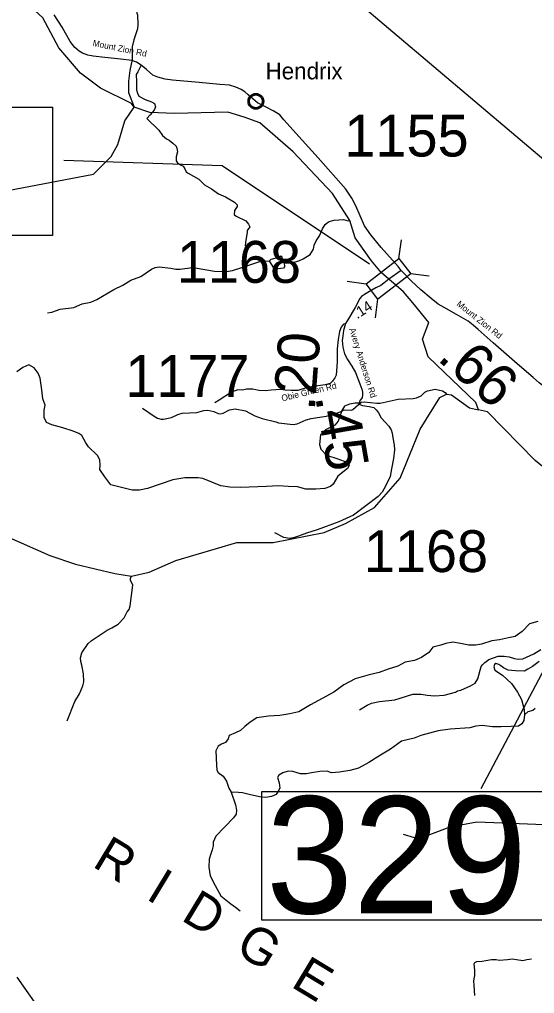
# Model space of a CAD drawing. Extents: x 1248224 to 1454986, y 825081 to 985870.
# Drawn here: x 1284414 to 1290579, y 869090 to 880743 of the extents above; entities that cross this region are included whole.
import ezdxf

# ---------------------------------------------------------------- set-up
doc = ezdxf.new("R2010")
doc.units = 0
for name, color, linetype in [('Exist Civil Demographics Community CELL', 7, 'Continuous'), ('Exist Civil Demographics Community Label', 7, 'Continuous'), ('Exist Geographical Mountain Summit Label', 7, 'Continuous'), ('Exist Hydrographic Creek Single Shore', 7, 'Continuous'), ('Exist Hydrographic Misc Water Feature', 7, 'Continuous'), ('Exist Road Non-System Type 51', 7, 'Continuous'), ('Exist Road Secondary Mileage Hundredths English Label', 7, 'Continuous'), ('Exist Road Secondary Structure Standard Bridge CELL', 7, 'Continuous'), ('Exist Road Secondary Structure Standard Bridge Number Label', 7, 'Continuous'), ('Exist Road Secondary Type 41 Attributed', 7, 'Continuous'), ('Exist Road Secondary Type 51 Attributed', 7, 'Continuous'), ('Exist Road Secondary Type 51 Label', 7, 'Continuous'), ('Exist Road Secondary Type 51 Number Label', 7, 'Continuous')]:
    doc.layers.add(name, color=color, linetype=linetype)

msp = doc.modelspace()

# ---------------------------------------------------------------- linework, layer by layer
at = {"layer": 'Exist Civil Demographics Community CELL'}
msp.add_lwpolyline([(1287166, 879777), (1287167, 879782), (1287169, 879789), (1287172, 879796), (1287175, 879802), (1287178, 879808), (1287182, 879813), (1287186, 879817), (1287190, 879822), (1287196, 879826), (1287201, 879830), (1287206, 879833), (1287211, 879835), (1287217, 879838), (1287222, 879840), (1287227, 879841), (1287231, 879841), (1287236, 879842), (1287242, 879842), (1287246, 879842), (1287252, 879842), (1287257, 879841), (1287262, 879840), (1287267, 879839), (1287272, 879837), (1287279, 879834), (1287285, 879831), (1287290, 879827), (1287295, 879823), (1287299, 879820), (1287303, 879815), (1287307, 879811), (1287310, 879806), (1287313, 879801), (1287315, 879796), (1287317, 879791), (1287319, 879786), (1287320, 879781), (1287321, 879775), (1287322, 879771), (1287322, 879765), (1287322, 879759), (1287321, 879753), (1287320, 879748), (1287319, 879742), (1287317, 879736), (1287315, 879731), (1287311, 879725), (1287308, 879719), (1287305, 879715), (1287300, 879710), (1287295, 879705), (1287290, 879701), (1287285, 879697), (1287281, 879695), (1287274, 879692), (1287267, 879689), (1287261, 879687), (1287254, 879686), (1287250, 879686), (1287245, 879685), (1287240, 879685), (1287235, 879686), (1287230, 879687), (1287224, 879688), (1287219, 879689), (1287214, 879691), (1287210, 879693), (1287206, 879695), (1287199, 879699), (1287193, 879704), (1287188, 879708), (1287184, 879713), (1287181, 879717), (1287178, 879721), (1287174, 879728), (1287172, 879732), (1287170, 879736), (1287168, 879744), (1287166, 879751), (1287165, 879756), (1287165, 879762), (1287165, 879767), (1287166, 879774)], close=True, dxfattribs=at)
for centre, radius in [((1287244, 879764), 94.3), ((1287243, 879765), 76.7)]:
    msp.add_circle(centre, radius, dxfattribs=at)
at = {"layer": 'Exist Hydrographic Creek Single Shore'}
for points in [[(1285786, 879695), (1285754, 879739), (1285383, 879923), (1285146, 880102), (1284886, 880403), (1284695, 880764), (1284597, 880852), (1284299, 880923), (1283948, 880907), (1283420, 881148)], [(1288835, 877637), (1288749, 877713), (1288629, 877856), (1288433, 878129), (1288367, 878339), (1288162, 878663), (1287691, 879158), (1287291, 879508), (1287103, 879576), (1286907, 879635), (1286268, 879617), (1285976, 879632), (1285786, 879695)], [(1289908, 876074), (1289877, 876160), (1289307, 876706), (1289237, 876918), (1289312, 877116), (1289122, 877354), (1289009, 877484), (1288835, 877637)], [(1292628, 873989), (1292480, 873916), (1292339, 873798), (1292149, 873939), (1291946, 874109), (1291864, 874236), (1291719, 874279), (1291609, 874359), (1291494, 874427), (1291324, 874630), (1291193, 874741), (1291112, 874855), (1291068, 875072), (1290585, 875466), (1290016, 876049), (1289908, 876074)], [(1284678, 868871), (1284388, 869284)]]:
    msp.add_lwpolyline(points, dxfattribs=at)
at = {"layer": 'Exist Hydrographic Misc Water Feature'}
for points in [[(1285848, 881734), (1285875, 881701), (1285910, 881636), (1285916, 881557), (1285882, 881393), (1285876, 881313), (1285822, 881184), (1285813, 881141), (1285813, 880884), (1285820, 880820), (1285827, 880800), (1285830, 880683), (1285825, 880632), (1285782, 880499), (1285762, 880416), (1285762, 880263), (1285733, 880134), (1285718, 880006), (1285720, 879870), (1285786, 879695)], [(1280564, 876573), (1281221, 877164), (1281561, 877423), (1281746, 877495), (1282014, 877535), (1282115, 877586), (1282277, 877730), (1282735, 878020), (1282961, 878088), (1283182, 878251), (1283385, 878361), (1283657, 878563), (1283766, 878603), (1285299, 878891), (1285513, 879103), (1285592, 879249), (1285674, 879530), (1285786, 879695)], [(1287582, 877831), (1287670, 877831), (1287758, 877857), (1287809, 877880), (1287894, 877931), (1287932, 877994), (1287941, 878042), (1287966, 878097), (1288004, 878156), (1288040, 878238), (1288073, 878289), (1288098, 878312), (1288122, 878328), (1288179, 878342), (1288291, 878350), (1288350, 878336), (1288367, 878339)], [(1287582, 877831), (1287570, 877847), (1287559, 877899), (1287543, 877912), (1287515, 877896), (1287422, 877871), (1287406, 877855)], [(1284749, 877232), (1284801, 877241), (1284902, 877278), (1285063, 877296), (1285164, 877342), (1285268, 877361), (1285341, 877392), (1285542, 877512), (1285652, 877566), (1285745, 877625), (1285866, 877667), (1285995, 877758), (1286039, 877776), (1286087, 877784), (1286227, 877770), (1286287, 877757), (1286339, 877756), (1286479, 877774), (1286515, 877773), (1286747, 877733), (1286891, 877730), (1286963, 877742), (1287076, 877775), (1287290, 877848), (1287406, 877855)], [(1287582, 877831), (1287588, 877785), (1287574, 877767), (1287484, 877757), (1287464, 877766), (1287406, 877855)], [(1284227, 874575), (1284779, 874332), (1285085, 874227), (1285557, 874113), (1285756, 874081), (1285966, 874131), (1286287, 874272), (1287017, 874487), (1287451, 874485), (1288063, 874604), (1288315, 874714), (1288662, 874904), (1288971, 875255), (1289210, 875842), (1289445, 876221), (1289526, 876262), (1289587, 876251), (1289800, 876096), (1289908, 876074)], [(1285888, 876093), (1286026, 875997), (1286065, 875974), (1286109, 875961), (1286137, 875961), (1286233, 875982), (1286310, 876019), (1286363, 876033), (1286535, 876043), (1286619, 876065), (1286668, 876068), (1286739, 876054), (1286791, 876029), (1286815, 876027), (1286851, 876033), (1286926, 876075), (1286994, 876086), (1287118, 876061), (1287230, 876002), (1287318, 875968), (1287481, 875930), (1287513, 875917), (1287688, 875898), (1287736, 875906), (1287846, 875953), (1287906, 875971), (1288083, 875997), (1288165, 876019), (1288266, 876053), (1288299, 876072), (1288387, 876071), (1288403, 876079), (1288505, 876165), (1288541, 876170), (1288693, 876151), (1288733, 876153), (1288947, 876202), (1289127, 876208), (1289167, 876215), (1289224, 876241), (1289267, 876286), (1289299, 876302), (1289388, 876319), (1289479, 876301), (1289511, 876282), (1289526, 876262)], [(1285159, 873165), (1285234, 873277), (1285271, 873310), (1285464, 873437), (1285521, 873463), (1285594, 873509), (1285668, 873585), (1285702, 873656), (1285725, 873683), (1285738, 873727), (1285770, 873975), (1285743, 874035), (1285744, 874057), (1285756, 874081)], [(1284985, 872354), (1285077, 872583), (1285131, 872676), (1285174, 872771), (1285185, 872819), (1285179, 872915), (1285162, 873020), (1285147, 873060), (1285146, 873104), (1285159, 873165)], [(1289986, 873049), (1290033, 873086), (1290142, 873127), (1290214, 873127), (1290274, 873118), (1290341, 873096), (1290385, 873091), (1290441, 873095), (1290571, 873152), (1290654, 873204)], [(1288483, 872484), (1288576, 872541), (1288629, 872564), (1288725, 872584), (1288906, 872603), (1289124, 872672), (1289224, 872673), (1289296, 872658), (1289383, 872652), (1289496, 872661), (1289633, 872696), (1289657, 872712), (1289697, 872718), (1289811, 872772), (1289869, 872804), (1289899, 872855), (1289939, 873004), (1289955, 873023), (1289986, 873049)], [(1289008, 870997), (1289140, 870955), (1289324, 870991), (1289569, 871084), (1289887, 871143), (1291103, 871096)]]:
    msp.add_lwpolyline(points, dxfattribs=at)
at = {"layer": 'Exist Road Non-System Type 51'}
for points in [[(1285869, 880195), (1285831, 880116), (1285812, 880086), (1285814, 879997), (1285814, 879902), (1285825, 879861), (1285844, 879826), (1285917, 879788), (1285996, 879758), (1286031, 879739), (1286042, 879698), (1286028, 879658), (1285977, 879604), (1285939, 879558), (1286080, 879421), (1286126, 879355), (1286175, 879315), (1286207, 879299), (1286248, 879263), (1286288, 879228), (1286299, 879204), (1286307, 879158), (1286288, 879101), (1286288, 879052), (1286305, 879027), (1286343, 879003), (1286372, 878989), (1286394, 878957), (1286410, 878922), (1286435, 878905), (1286559, 878832), (1286627, 878767), (1286714, 878716), (1286798, 878656), (1286879, 878621), (1286987, 878556), (1287019, 878524), (1287019, 878505), (1286989, 878457), (1286984, 878410), (1287008, 878389), (1287122, 878335), (1287157, 878294), (1287171, 878264), (1287141, 878218), (1287138, 878199), (1287119, 878077), (1287117, 878031)], [(1288481, 876154), (1288434, 876153), (1288365, 876142), (1288304, 876117), (1288271, 876066), (1288227, 875939), (1288187, 875888), (1288078, 875833), (1288017, 875775), (1288006, 875659), (1288020, 875601), (1288089, 875532), (1288213, 875492), (1288300, 875459), (1288351, 875441), (1288362, 875408), (1288340, 875372), (1288224, 875281), (1288169, 875183), (1288137, 875157), (1288071, 875132), (1287962, 875125), (1287842, 875125), (1287741, 875150), (1287632, 875157), (1287515, 875165), (1287370, 875154), (1287061, 875143), (1286931, 875146), (1286825, 875165), (1286607, 875252), (1286553, 875259), (1286393, 875259), (1286251, 875237), (1285946, 875132), (1285850, 875110), (1285762, 875110), (1285508, 875176), (1285435, 875270), (1285377, 875361), (1285381, 875412), (1285374, 875474), (1285348, 875528), (1285239, 875630), (1285210, 875677), (1285159, 875764), (1285123, 875790), (1285058, 875819), (1284934, 875859), (1284803, 875892), (1284738, 875921), (1284709, 875983), (1284709, 876070), (1284720, 876128), (1284694, 876204), (1284681, 876312), (1284663, 876450), (1284637, 876512), (1284590, 876574), (1284524, 876610), (1284452, 876581), (1284383, 876526)], [(1287835, 876332), (1287744, 876304), (1287667, 876304), (1287593, 876310), (1287537, 876316), (1287425, 876310), (1287360, 876301), (1287280, 876304), (1287209, 876322), (1287130, 876319), (1287085, 876307), (1287029, 876313), (1286952, 876286), (1286805, 876189), (1286752, 876156)], [(1288709, 875038), (1288413, 874814), (1288236, 874732), (1287976, 874637), (1287849, 874596), (1287754, 874563), (1287692, 874542), (1287645, 874534), (1287577, 874545), (1287471, 874602)], [(1290619, 873540), (1290519, 873511), (1290430, 873422), (1290347, 873363), (1290268, 873345), (1290158, 873321), (1290067, 873310), (1289943, 873268), (1289875, 873256), (1289792, 873256), (1289692, 873277), (1289603, 873295), (1289518, 873277), (1289459, 873259), (1289395, 873242), (1289363, 873232), (1289315, 873170)], [(1289315, 873170), (1289228, 873109), (1289142, 873075), (1289029, 873055), (1288943, 873008), (1288828, 872971), (1288718, 872932), (1288601, 872904), (1288433, 872853), (1288295, 872781), (1288175, 872696), (1287899, 872543), (1287756, 872459), (1287652, 872434), (1287531, 872417), (1287394, 872408), (1287257, 872386), (1287175, 872335), (1287111, 872285), (1287060, 872237), (1286999, 872209), (1286923, 872176), (1286912, 872136), (1286881, 872091), (1286833, 872072), (1286794, 872049), (1286763, 871993), (1286772, 871822), (1286778, 871762), (1286792, 871734), (1286851, 871692), (1286890, 871630), (1286918, 871546), (1286946, 871500)], [(1290633, 873061), (1290555, 873002), (1290498, 872969), (1290458, 872946), (1290352, 872949), (1290265, 872960), (1290206, 872986), (1290175, 873011), (1290150, 873028), (1290117, 873039), (1290100, 873028), (1290091, 872997), (1290105, 872960), (1290195, 872899), (1290304, 872800), (1290377, 872694), (1290422, 872607), (1290456, 872486), (1290461, 872422), (1290450, 872357), (1290428, 872315), (1290388, 872287), (1290299, 872284), (1290181, 872282), (1290077, 872282), (1289951, 872296), (1289875, 872287), (1289803, 872268), (1289570, 872251), (1289424, 872234), (1289220, 872175), (1289140, 872145), (1288985, 872108), (1288856, 872013), (1288736, 871940), (1288596, 871853), (1288473, 871787), (1288370, 871756), (1288246, 871736), (1288148, 871728), (1288095, 871750), (1288011, 871744), (1287910, 871730), (1287848, 871716), (1287778, 871719), (1287686, 871744), (1287632, 871750), (1287568, 871728), (1287520, 871700), (1287504, 871674), (1287523, 871610), (1287529, 871548)], [(1290588, 872498), (1290557, 872477), (1290500, 872459), (1290461, 872422)], [(1286946, 871500), (1287000, 871347), (1287011, 871282), (1287008, 871237), (1286977, 871190), (1286764, 870971), (1286733, 870900), (1286733, 870858), (1286719, 870807), (1286702, 870748), (1286683, 870698), (1286680, 870600)], [(1287529, 871548), (1287509, 871509), (1287487, 871472), (1287431, 871447), (1287361, 871433), (1287288, 871442), (1287164, 871472), (1287083, 871492), (1287035, 871495), (1286946, 871500)], [(1286680, 870600), (1286697, 870496), (1286756, 870381), (1286826, 870258), (1286944, 870162), (1287000, 870123), (1287056, 870078)], [(1289864, 869067), (1289855, 869191), (1289853, 869239), (1289858, 869267), (1289866, 869306), (1289866, 869364), (1289860, 869410), (1289858, 869445), (1289866, 869461), (1289887, 869472), (1289952, 869477), (1289998, 869484), (1290065, 869497), (1290119, 869497), (1290156, 869488), (1290257, 869498), (1290310, 869504), (1290365, 869498), (1290439, 869486), (1290488, 869495), (1290543, 869505)]]:
    msp.add_lwpolyline(points, dxfattribs=at)
at = {"layer": 'Exist Road Secondary Structure Standard Bridge CELL'}
for p, q in [((1288956, 877884), (1288985, 878109)), ((1289094, 877705), (1289319, 877676)), ((1288338, 877611), (1288563, 877582)), ((1288675, 877174), (1288704, 877399))]:
    msp.add_line(p, q, dxfattribs=at)
msp.add_lwpolyline([(1288563, 877582), (1288956, 877885), (1289097, 877702), (1288704, 877399)], close=True, dxfattribs=at)
at = {"layer": 'Exist Road Secondary Structure Standard Bridge Number Label'}
for p, q in [((1290948, 878846), (1286961, 882217)), ((1292009, 875464), (1289936, 871537))]:
    msp.add_line(p, q, dxfattribs=at)
for points in [[(1281094, 879694), (1284810, 879694), (1284810, 878158), (1281094, 878158)], [(1287315, 871506), (1291031, 871506), (1291031, 869969), (1287315, 869969)]]:
    msp.add_lwpolyline(points, close=True, dxfattribs=at)
msp.add_lwpolyline([(1288603, 877815), (1286839, 878991), (1284944, 879057)], dxfattribs=at)
at = {"layer": 'Exist Road Secondary Type 41 Attributed'}
for points in [[(1288982, 877742), (1288835, 877637)], [(1288835, 877637), (1288777, 877588), (1288739, 877562), (1288681, 877531), (1288585, 877476), (1288542, 877451), (1288509, 877429), (1288487, 877407), (1288432, 877297), (1288344, 877148), (1288316, 877105)], [(1288316, 877105), (1288293, 877022), (1288283, 876958), (1288275, 876902), (1288285, 876824), (1288306, 876745), (1288340, 876674), (1288393, 876595), (1288436, 876518), (1288487, 876386), (1288513, 876321), (1288518, 876284), (1288520, 876254), (1288515, 876217), (1288487, 876184), (1288481, 876154), (1288489, 876136), (1288518, 876125), (1288601, 876113), (1288656, 876102), (1288687, 876071), (1288713, 876037), (1288742, 875976), (1288793, 875925), (1288836, 875878), (1288864, 875835), (1288876, 875793), (1288885, 875738), (1288899, 875656), (1288901, 875595), (1288891, 875490), (1288868, 875366), (1288850, 875277), (1288797, 875161), (1288757, 875088), (1288709, 875038)]]:
    msp.add_lwpolyline(points, dxfattribs=at)
at = {"layer": 'Exist Road Secondary Type 51 Attributed'}
for points in [[(1288982, 877742), (1288945, 877786), (1288745, 878014), (1288621, 878168), (1288545, 878273), (1288441, 878514), (1288392, 878606), (1288320, 878712), (1287990, 879088), (1287799, 879298), (1287580, 879542), (1287532, 879601), (1287451, 879650), (1287357, 879697), (1287265, 879745), (1287151, 879840), (1287113, 879877), (1287067, 879907), (1287002, 879935), (1286926, 879957), (1286813, 879967), (1286566, 879988), (1286245, 880017), (1286156, 880028), (1286071, 880052), (1286010, 880078), (1285934, 880145), (1285869, 880195), (1285814, 880234), (1285757, 880251), (1285627, 880268), (1285437, 880288), (1285296, 880305), (1285232, 880317), (1285170, 880340), (1285128, 880366), (1285078, 880410), (1285022, 880478), (1284923, 880650), (1284828, 880798)], [(1291859, 875829), (1291575, 875951), (1291381, 876030), (1291219, 876097), (1290989, 876191), (1290851, 876257), (1290755, 876313), (1290697, 876347), (1290635, 876396), (1290561, 876460), (1290372, 876625), (1290085, 876874), (1289903, 877035), (1289843, 877086), (1289784, 877134), (1289645, 877214), (1289498, 877296), (1289424, 877339), (1289342, 877404), (1289218, 877508), (1289101, 877618), (1288982, 877742)], [(1288316, 877105), (1288290, 877094), (1288266, 877063), (1288245, 877010), (1288229, 876915), (1288215, 876801), (1288217, 876648), (1288209, 876541), (1288203, 876489), (1288188, 876456), (1288160, 876416), (1288131, 876389), (1288074, 876371), (1287928, 876351), (1287835, 876332)]]:
    msp.add_lwpolyline(points, dxfattribs=at)

# ---------------------------------------------------------------- texts
at = {"layer": 'Exist Civil Demographics Community Label'}
msp.add_text('Hendrix', height=200, dxfattribs=at).set_placement((1287360, 880027))
at = {"layer": 'Exist Geographical Mountain Summit Label'}
msp.add_text('R  I  D  G  E', height=440, rotation=328.8202, dxfattribs=at).set_placement((1285272, 870617))
at = {"layer": 'Exist Road Secondary Mileage Hundredths English Label'}
for s, height, rotation, p in [('.14', 125, 32.9261, (1288457, 877156)), ('.20', 500, 85.7669, (1287948, 876055)), ('.66', 500, 319.0006, (1289401, 876676)), ('.45', 500, 279.897, (1287952, 876231))]:
    msp.add_text(s, height=height, rotation=rotation, dxfattribs=at).set_placement(p)
at = {"layer": 'Exist Road Secondary Structure Standard Bridge Number Label'}
msp.add_text('329', height=1400, dxfattribs=at).set_placement((1287365, 870048))
at = {"layer": 'Exist Road Secondary Type 51 Label'}
for s, rotation, p in [('Mount Zion Rd', 348.4382, (1285285, 880428)), ('Mount Zion Rd', 321.5794, (1289640, 877326)), ('Avery Anderson Rd', 287.4079, (1288359, 877039)), ('Obie Green Rd', 13.4258, (1287559, 876174))]:
    msp.add_text(s, height=75, rotation=rotation, dxfattribs=at).set_placement(p)
at = {"layer": 'Exist Road Secondary Type 51 Number Label'}
for s, p in [('1155', (1288303, 879104)), ('1168', (1286297, 877593)), ('1177', (1285680, 876228)), ('1168', (1288536, 874132))]:
    msp.add_text(s, height=500, dxfattribs=at).set_placement(p)

doc.saveas('drawing.dxf')
